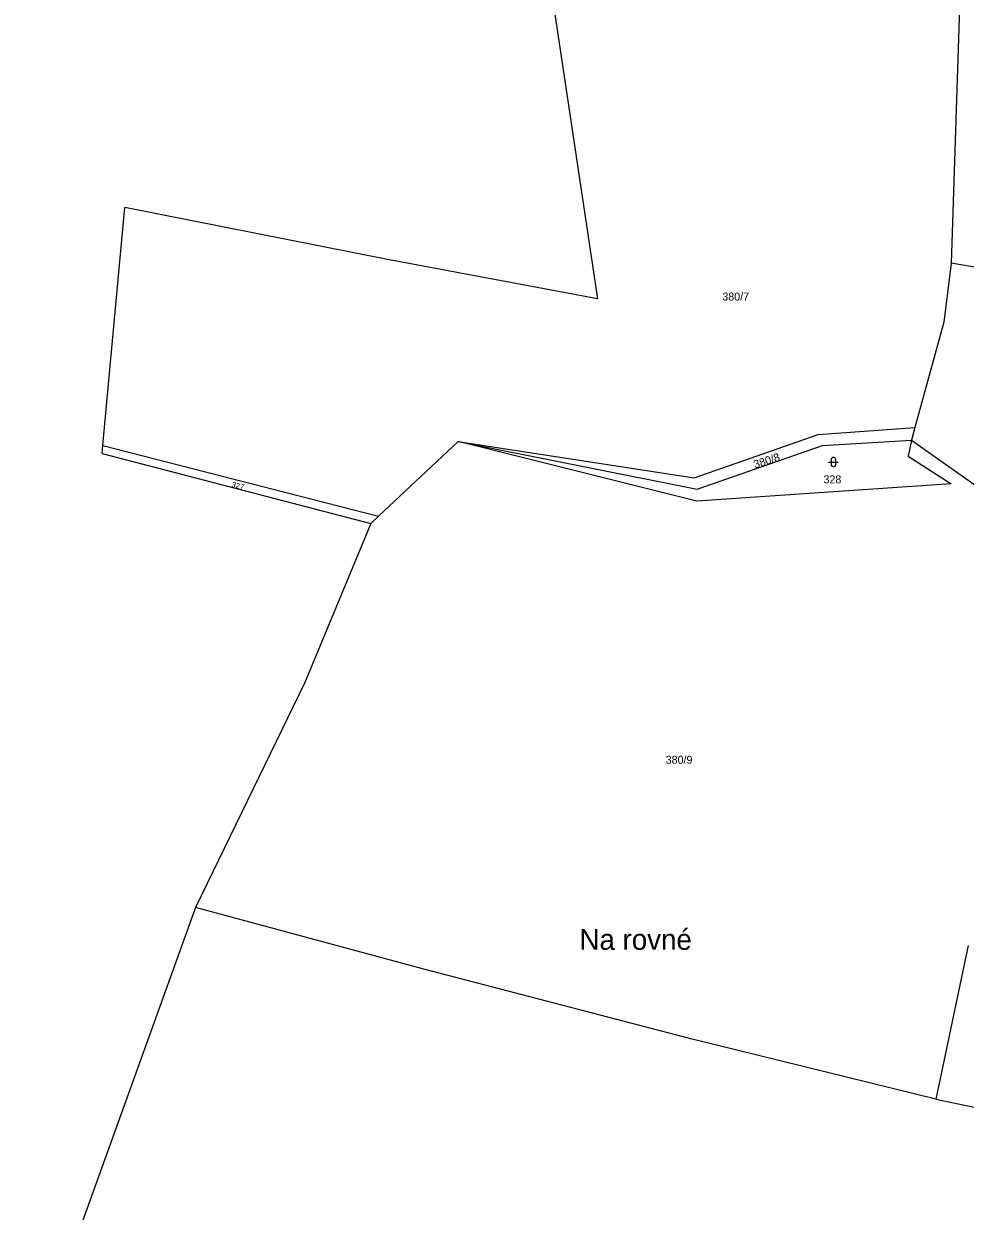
# Model space of a CAD drawing. Extents: x -791548 to -789311, y -1142631 to -1140855.
# Drawn here: x -791182.6 to -790982.6, y -1142211.2 to -1141959 of the extents above; entities that cross this region are included whole.
import ezdxf
from ezdxf.enums import TextEntityAlignment as Align

# ---------------------------------------------------------------- set-up
doc = ezdxf.new("R2010")
doc.units = 0
doc.header["$LTSCALE"] = 0.68
for name, color, linetype, lineweight in [('1', 7, 'Continuous', 25), ('3', 7, 'Continuous', 25), ('7', 7, 'Continuous', 13)]:
    doc.layers.add(name, color=color, linetype=linetype, lineweight=lineweight)
doc.layers.add('2', color=7, linetype='Continuous')

msp = doc.modelspace()

# ---------------------------------------------------------------- linework, layer by layer
at = {"layer": '1'}
for p, q in [((-790983.28, -1141938.11), (-790985.61, -1142009.88)), ((-791069.8, -1141956.97), (-791060.76, -1142017.45)), ((-791165.83, -1142048.59), (-791161.15, -1141998.03)), ((-791105.74, -1142008.99), (-791161.15, -1141998.03)), ((-791060.76, -1142017.45), (-791105.74, -1142008.99)), ((-790985.61, -1142009.88), (-790987.16, -1142022.41)), ((-790954.25, -1142015.12), (-790985.61, -1142009.88)), ((-790987.16, -1142022.41), (-790993.32, -1142044.74)), ((-791040.19, -1142055.43), (-791013.87, -1142046.23)), ((-791013.87, -1142046.23), (-790993.32, -1142044.74)), ((-790993.32, -1142044.74), (-790994.07, -1142047.46)), ((-791165.98, -1142050.25), (-791165.83, -1142048.59)), ((-791165.83, -1142048.59), (-791107.25, -1142063.61)), ((-791090.36, -1142047.77), (-791107.25, -1142063.61)), ((-791090.36, -1142047.77), (-791039.59, -1142057.83)), ((-791039.67, -1142060.43), (-791090.36, -1142047.77)), ((-791090.36, -1142047.77), (-791040.19, -1142055.43)), ((-791039.59, -1142057.83), (-791012.94, -1142048.58)), ((-791012.94, -1142048.58), (-790994.07, -1142047.46)), ((-790994.07, -1142047.46), (-790994.73, -1142050.82)), ((-790994.07, -1142047.46), (-790965.09, -1142067.97)), ((-791165.98, -1142050.25), (-791108.89, -1142065.15)), ((-790994.73, -1142050.82), (-790985.65, -1142056.73)), ((-790985.65, -1142056.73), (-791039.67, -1142060.43)), ((-791107.25, -1142063.61), (-791108.89, -1142065.15)), ((-791108.89, -1142065.15), (-791122.9, -1142098.94)), ((-791122.9, -1142098.94), (-791146.13, -1142146.74)), ((-791146.13, -1142146.74), (-791182.62, -1142247.78)), ((-791097.63, -1142159.81), (-791146.13, -1142146.74)), ((-790981.99, -1142154.78), (-790988.86, -1142187.43)), ((-791040.62, -1142174.67), (-791097.63, -1142159.81)), ((-790988.86, -1142187.43), (-791040.62, -1142174.67)), ((-790988.86, -1142187.43), (-790930.11, -1142199.76))]:
    msp.add_line(p, q, dxfattribs=at)
at = {"layer": '3'}
for p, q in [((-791011.151, -1142051.601), (-791011.151, -1142052.602)), ((-791010.149, -1142052.602), (-791010.149, -1142051.601)), ((-791011.651, -1142052.101), (-791009.649, -1142052.101))]:
    msp.add_line(p, q, dxfattribs=at)
for centre, start, end in [((-791010.65, -1142051.6009), 0, 180), ((-791010.65, -1142052.6009), 180, 359.98789)]:
    msp.add_arc(centre, 0.5, start, end, dxfattribs=at)

# ---------------------------------------------------------------- texts
at = {"layer": '2'}
for s, p in [('380/7', (-791031.39, -1142017.802)), ('328', (-791010.859, -1142056.632)), ('380/9', (-791043.42, -1142116.182))]:
    msp.add_text(s, height=1.7, dxfattribs=at).set_placement(p, align=Align.CENTER)
msp.add_text('380/8', height=1.7, rotation=18, dxfattribs=at).set_placement((-791024.5587, -1142052.606), align=Align.CENTER)
at = {"layer": '2', "width": 1.05}
msp.add_text('327', height=1.14, rotation=347, dxfattribs=at).set_placement((-791137.2582, -1142057.6823), align=Align.CENTER)
at = {"layer": '7'}
msp.add_text('Na rovné', height=4.4, dxfattribs=at).set_placement((-791064.58, -1142155.71))

doc.saveas('drawing.dxf')
